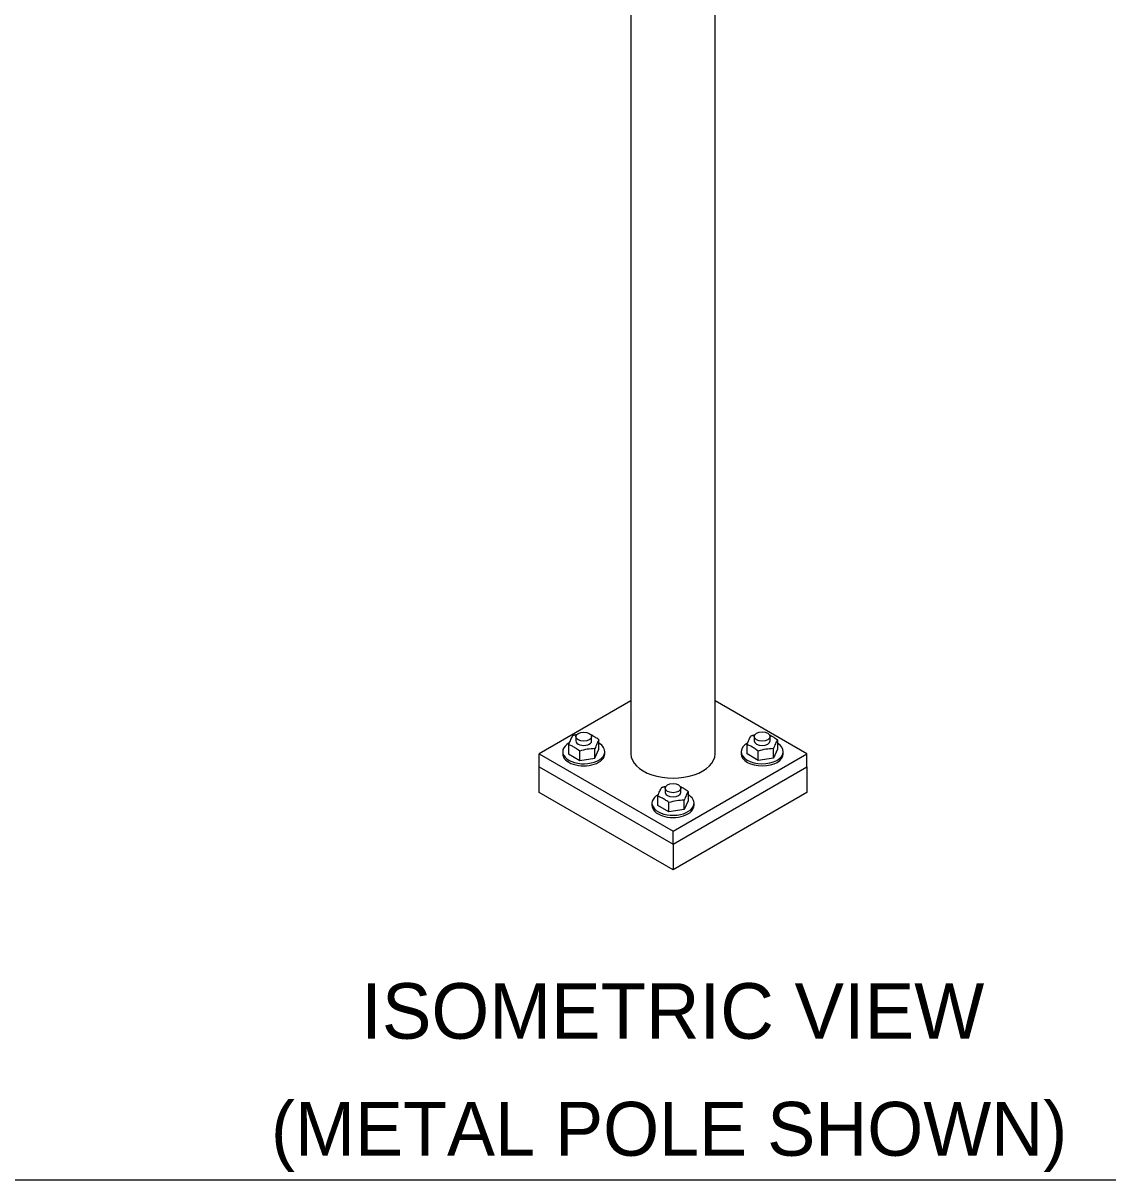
# Model space of a CAD drawing. Extents: x 99862 to 103151, y 100000 to 105076.
# Drawn here: x 102188.2 to 102510.5, y 99999.5 to 100343 of the extents above; entities that cross this region are included whole.
import ezdxf

# ---------------------------------------------------------------- set-up
doc = ezdxf.new("R2010")
doc.units = 0
for name, color, linetype in [('Level 1', 7, 'Continuous'), ('Level 20', 7, 'Continuous'), ('Level 31', 7, 'Continuous'), ('Level 4', 7, 'Continuous'), ('Level 5', 7, 'Continuous'), ('Level 6', 7, 'Continuous'), ('Level 7', 7, 'Continuous')]:
    doc.layers.add(name, color=color, linetype=linetype)

msp = doc.modelspace()

# ---------------------------------------------------------------- linework, layer by layer
at = {"layer": 'Level 1'}
msp.add_lwpolyline([(99862, 99999.5), (103151, 99999.5), (103151, 102075.5), (99862, 102075.5)], close=True, dxfattribs=at)
at = {"layer": 'Level 31'}
for p, q in [((102393.78, 100126.02), (102393.78, 100657.75)), ((102368.78, 100415.75), (102368.78, 100126.02))]:
    msp.add_line(p, q, dxfattribs=at)
msp.add_ellipse((102381.28, 100126.02), major_axis=(12.5, 0), ratio=0.57735, start_param=3.14158, end_param=6.283185, dxfattribs=at)
at = {"layer": 'Level 4'}
for p, q in [((102352.42, 100131.14), (102352.42, 100129.86)), ((102357.11, 100129.86), (102357.11, 100131.14)), ((102405.42, 100131.16), (102405.42, 100129.88)), ((102410.1, 100129.88), (102410.1, 100131.16)), ((102378.93, 100115.83), (102378.93, 100114.55)), ((102383.62, 100114.55), (102383.62, 100115.83))]:
    msp.add_line(p, q, dxfattribs=at)
for centre, major_axis in [((102354.76, 100131.14), (-2.34, 0)), ((102407.76, 100131.16), (2.34, 0)), ((102381.28, 100115.83), (2.34, 0))]:
    msp.add_ellipse(centre, major_axis=major_axis, ratio=0.57735, dxfattribs=at)
at = {"layer": 'Level 5'}
for p, q in [((102368.78, 100141.77), (102341.5, 100126.02)), ((102421.05, 100126.02), (102393.78, 100141.77)), ((102341.5, 100122.2), (102341.5, 100126.02)), ((102341.5, 100126.02), (102341.5, 100126.02)), ((102341.5, 100126.02), (102381.28, 100103.06)), ((102381.28, 100103.06), (102421.05, 100126.02)), ((102421.05, 100122.2), (102421.05, 100126.02)), ((102421.05, 100126.02), (102421.05, 100126.02)), ((102381.28, 100099.23), (102381.28, 100103.06))]:
    msp.add_line(p, q, dxfattribs=at)
at = {"layer": 'Level 6'}
for p, q in [((102341.5, 100114.54), (102341.5, 100122.2)), ((102341.5, 100122.2), (102381.28, 100099.23)), ((102381.28, 100099.23), (102421.05, 100122.2)), ((102421.05, 100122.2), (102421.05, 100122.2)), ((102421.05, 100122.2), (102421.05, 100114.54)), ((102381.28, 100091.58), (102341.5, 100114.54)), ((102421.05, 100114.54), (102381.28, 100091.58)), ((102381.28, 100099.23), (102381.28, 100091.58))]:
    msp.add_line(p, q, dxfattribs=at)
at = {"layer": 'Level 7'}
for p, q in [((102359.29, 100127.37), (102359.29, 100130.16)), ((102412.32, 100130.16), (102412.32, 100127.37)), ((102348.51, 100126.67), (102348.51, 100126.04)), ((102350.23, 100128.76), (102350.23, 100125.97)), ((102353.55, 100124.06), (102353.55, 100126.85)), ((102358.08, 100124.76), (102358.08, 100127.55)), ((102358.08, 100124.76), (102359.29, 100127.37)), ((102361.01, 100126.04), (102361.01, 100126.67)), ((102401.54, 100126.67), (102401.54, 100126.04)), ((102403.27, 100125.97), (102403.27, 100128.76)), ((102406.58, 100124.06), (102406.58, 100126.85)), ((102411.11, 100124.76), (102411.11, 100127.55)), ((102412.32, 100127.37), (102411.11, 100124.76)), ((102414.04, 100126.04), (102414.04, 100126.67)), ((102350.23, 100125.97), (102353.55, 100124.06)), ((102353.55, 100124.06), (102358.08, 100124.76)), ((102406.58, 100124.06), (102403.27, 100125.97)), ((102411.11, 100124.76), (102406.58, 100124.06)), ((102376.75, 100110.66), (102376.75, 100113.45)), ((102385.81, 100114.85), (102385.81, 100112.06)), ((102375.03, 100111.36), (102375.03, 100110.73)), ((102380.07, 100108.75), (102376.75, 100110.66)), ((102380.07, 100108.75), (102380.07, 100111.54)), ((102384.59, 100109.45), (102380.07, 100108.75)), ((102384.59, 100109.45), (102384.59, 100112.24)), ((102385.81, 100112.06), (102384.59, 100109.45)), ((102387.53, 100110.73), (102387.53, 100111.36))]:
    msp.add_line(p, q, dxfattribs=at)
for centre, major_axis, start_param, end_param in [((102354.76, 100129.86), (2.34, 0), 3.141593, 6.283187), ((102407.76, 100129.88), (2.34, 0), 3.141605, 6.283185), ((102354.76, 100126.67), (6.25, 0), 2.335626, 6.194681), ((102354.76, 100126.67), (6.25, 0), 6.194681, 7.043754), ((102407.79, 100126.67), (6.25, 0), 2.335626, 7.043754), ((102354.76, 100126.04), (6.25, 0), 3.14158, 6.283185), ((102407.79, 100126.04), (6.25, 0), 3.141593, 6.28318), ((102381.28, 100111.36), (6.25, 0), 2.335626, 6.194681), ((102381.28, 100114.55), (2.34, 0), 3.141593, 6.28318), ((102381.28, 100111.36), (6.25, 0), 6.194681, 7.043754), ((102381.28, 100110.73), (6.25, 0), 3.14158, 6.283185)]:
    msp.add_ellipse(centre, major_axis=major_axis, ratio=0.57735, start_param=start_param, end_param=end_param, dxfattribs=at)
for points, degree in [([(102351.45, 100131.37), (102351.24, 100131.04), (102350.84, 100130.29), (102350.44, 100129.3), (102350.23, 100128.76)], 3), ([(102352.61, 100131.67), (102352.22, 100131.59), (102351.83, 100131.48), (102351.45, 100131.37)], 2), ([(102359.29, 100130.16), (102358.74, 100130.58), (102358.18, 100130.96), (102357.39, 100131.42), (102357.16, 100131.54), (102356.93, 100131.65)], 3), ([(102359.29, 100130.16), (102359.09, 100129.83), (102358.68, 100129.08), (102358.28, 100128.08), (102358.08, 100127.55)], 3), ([(102403.27, 100128.76), (102403.47, 100129.3), (102403.87, 100130.29), (102404.28, 100131.04), (102404.48, 100131.37)], 3), ([(102404.48, 100131.37), (102404.85, 100131.48), (102405.22, 100131.58), (102405.58, 100131.66)], 2), ([(102409.93, 100131.67), (102410.17, 100131.55), (102410.42, 100131.42), (102411.21, 100130.96), (102411.77, 100130.58), (102412.32, 100130.16)], 3), ([(102412.32, 100130.16), (102412.12, 100129.83), (102411.72, 100129.08), (102411.31, 100128.08), (102411.11, 100127.55)], 3), ([(102353.55, 100126.85), (102353, 100127.26), (102352.44, 100127.65), (102351.33, 100128.29), (102350.78, 100128.54), (102350.23, 100128.76)], 3), ([(102358.08, 100127.55), (102357.32, 100127.53), (102355.81, 100127.42), (102354.3, 100127.06), (102353.55, 100126.85)], 3), ([(102406.58, 100126.85), (102406.03, 100127.26), (102405.47, 100127.65), (102404.37, 100128.29), (102403.82, 100128.54), (102403.27, 100128.76)], 3), ([(102411.11, 100127.55), (102410.35, 100127.53), (102408.85, 100127.42), (102407.34, 100127.06), (102406.58, 100126.85)], 3), ([(102376.75, 100113.45), (102376.95, 100113.99), (102377.36, 100114.98), (102377.76, 100115.73), (102377.96, 100116.06)], 3), ([(102377.96, 100116.06), (102378.35, 100116.18), (102378.74, 100116.28), (102379.13, 100116.36)], 2), ([(102383.45, 100116.34), (102383.68, 100116.23), (102383.91, 100116.11), (102384.7, 100115.65), (102385.25, 100115.27), (102385.81, 100114.85)], 3), ([(102380.07, 100111.54), (102379.51, 100111.96), (102378.96, 100112.34), (102377.85, 100112.98), (102377.3, 100113.23), (102376.75, 100113.45)], 3), ([(102385.81, 100114.85), (102385.6, 100114.52), (102385.2, 100113.77), (102384.8, 100112.77), (102384.59, 100112.24)], 3), ([(102384.59, 100112.24), (102383.84, 100112.22), (102382.33, 100112.11), (102380.82, 100111.75), (102380.07, 100111.54)], 3)]:
    msp.add_open_spline(points, degree=degree, dxfattribs=at)

# ---------------------------------------------------------------- texts
at = {"layer": 'Level 20'}
for s, height, p in [('ISOMETRIC VIEW', 16.5, (102288.66, 100041.41)), ('(METAL POLE SHOWN)', 16, (102261.84, 100006.66))]:
    msp.add_text(s, height=height, dxfattribs=at).set_placement(p)

doc.saveas('drawing.dxf')
